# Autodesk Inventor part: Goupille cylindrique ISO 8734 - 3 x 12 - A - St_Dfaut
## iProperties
Created: 2007-07
Part Number: Goupille cylindrique ISO 8734 - 3 x 12 - A - St_Dfaut
Document SubType Name: Modeling
Designer: EF
Density: 1 g/cm^3
Author: EF
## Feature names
1. Base1
